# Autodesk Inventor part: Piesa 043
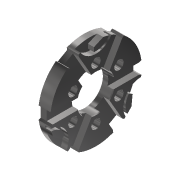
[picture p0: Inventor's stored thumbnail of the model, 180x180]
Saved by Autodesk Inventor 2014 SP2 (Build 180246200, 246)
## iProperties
Created: 2009-01
Part Number: Piesa 043
Document SubType Name: Modeling
Designer: Costel
Material: Steel
Density: 7.85 g/cm^3
Appearance: Steel - Polished
Author: Costel
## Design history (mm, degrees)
sketch "Sketch2"
  geometry: L1 (-95.423, 0)-(118.595, 0) reference; L2 (0, -82.8)-(0, 110.4) reference; L3 (-48, -8)-(-48, 8); L4 (-65.156, 8)-(-68.345, 9.487); L5 (-65.156, -8)-(-68.345, -9.487); L6 (-65.156, -8)-(-65.156, 8); L7 (-39.506, -52.427)-(-42.388, -54.445); L8 (-25.65, -60.427)-(-25.956, -63.932); L9 (-25.65, -60.427)-(-39.506, -52.427); L10 (25.65, -60.427)-(25.956, -63.932); L11 (39.506, -52.427)-(42.388, -54.445); L12 (39.506, -52.427)-(25.65, -60.427); L13 (65.156, -8)-(68.345, -9.487); L14 (65.156, 8)-(68.345, 9.487); L15 (65.156, 8)-(65.156, -8); L16 (39.506, 52.427)-(42.388, 54.445); L17 (25.65, 60.427)-(25.956, 63.932); L18 (25.65, 60.427)-(39.506, 52.427); L19 (-25.65, 60.427)-(-25.956, 63.932); L20 (-39.506, 52.427)-(-42.388, 54.445); L21 (-39.506, 52.427)-(-25.65, 60.427); A1 r 69 centre (0, 0) between (-42.388, 54.445) and (-68.345, 9.487); A2 r 69 centre (0, 0) between (25.956, 63.932) and (-25.956, 63.932); A3 r 69 centre (0, 0) between (68.345, 9.487) and (42.388, 54.445); A4 r 69 centre (0, 0) between (42.388, -54.445) and (68.345, -9.487); A5 r 69 centre (0, 0) between (-68.345, -9.487) and (-42.388, -54.445); A6 r 69 centre (0, 0) between (-25.956, -63.932) and (25.956, -63.932); 2 further points
  constraints: 38 end point, 12 point on circle, 6 centre point, 2 parallel, 2 point on line, 1 symmetric about line, 43 other
  dimensions: "d1" = 48 distance between parallel lines of L2 L3; "d3" = 50 deg angle of L5 L4; "d4" = 16 distance of L5.start L4.start; "d7" = 360 deg dimension on A1.centre L4.start (derived); "d9" = 69 radius of A1
extrude "Extrusion1" new body sketch "Sketch2" distance "d10" = 18; taper "d11" = 0 deg
hole "Hole1" diameter "d14" = 55; stored, may be unused: countersink angle "d18" = 90 deg, drill point angle "d20" = 118 deg; dims "d12" = 10, "d13" = 10, "d15" = 6, "d16" = 4, "d17" = 2, "d19" = 8
chamfer "Chamfer1" distance "d21" = 1; stored, may be unused: second distance "d22" = 2, angle "d23" = 45 deg
sketch "Sketch3"
  geometry: L1 (-8, -65.156)-(8, -65.156) reference; L2 (8, 65.156)-(-8, 65.156) reference; L3 (-8, -65.156)-(-8, -26.311); L4 (8, -65.156)-(8, -26.311); L5 (8, -65.156)-(-8, -65.156); A1 r 27.5 centre (0, 0) between (-8, -26.311) and (8, -26.311) reference; A2 r 27.5 centre (0, 0) between (-8, -26.311) and (8, -26.311)
  constraints: 6 end point, 4 point on circle, 2 equal length, 1 centre point, 1 coincident, 1 perpendicular
extrude "Extrusion2" cut sketch "Sketch3" distance "d24" = 9; taper "d25" = 0 deg
pattern_circular "Circular Pattern1" dims angle "d27" = 360 deg
sketch "Sketch4"
  geometry: L1 (-63.932, -25.956)-(-60.427, -25.65) reference; L2 (0, -82.014)-(0, 109.352) reference; L3 (82.8, 0)-(-110.4, 0) reference; L4 (-61.927, -3)-(-68.129, 10.929); L5 (-61.927, -3)-(-55.442, -3); A1 r 28.5 centre (0, 0) between (-27.689, 6.749) and (-27.689, -6.749) reference; A2 r 69 centre (0, 0) between (-63.932, 25.956) and (-63.932, -25.956) reference; A3 r 23.5 centre (-78.75, 0) between (-55.442, -3) and (-66.097, 19.803); A4 r 27 centre (-78.75, 0) between (-64.975, -23.222) and (-64.975, 23.222); A5 r 69 centre (0, 0) between (-64.975, 23.222) and (-66.097, 19.803); A6 r 69 centre (0, 0) between (-68.129, 10.929) and (-64.975, -23.222); 1 further point
  constraints: 11 point on circle, 5 end point, 4 centre point, 2 coincident, 1 point on line
  dimensions: "d32" = 27 radius of A4; "d33" = 23.5 radius of A3; "d34" = 3 distance between parallel lines of L3 L5; "d35" = 66 deg angle of L3 L4; "d36" = 62 distance of A1.centre L4.start; "d37" = 78.75 distance of A2.centre A4.centre; "d38" = 69 radius of A5
extrude "Extrusion3" cut sketch "Sketch4" distance "d39" = 9 (= d24); taper "d40" = 0 deg
pattern_circular "Circular Pattern2" dims angle "d42" = 360 deg
sketch "Sketch5"
  geometry: L1 (83.775, 0)-(-123.075, 0) reference; A1 r 69 centre (0, 0) between (-64.975, -23.222) and (-63.932, -25.956) reference; 6 further points
  constraints: 1 point on line, 7 other
  dimensions: "d44" = 40 distance of point (-40, 0) A1.centre; "d47" = 360 deg dimension on A1.centre point (-40, 0) (derived)
hole "Hole2" sketch "Sketch5" at (-40, 0), (-20, -34.641), (20, -34.641), (40, 0), (20, 34.641), (-20, 34.641) diameter "d49" = 9; stored, may be unused: countersink angle "d53" = 90 deg, drill point angle "d55" = 118 deg; dims "d50" = 6, "d51" = 14, "d52" = 9, "d54" = 8
body "Solid1"
other parameters: "d0" = 138, "d30" = 54, "d31" = 47
